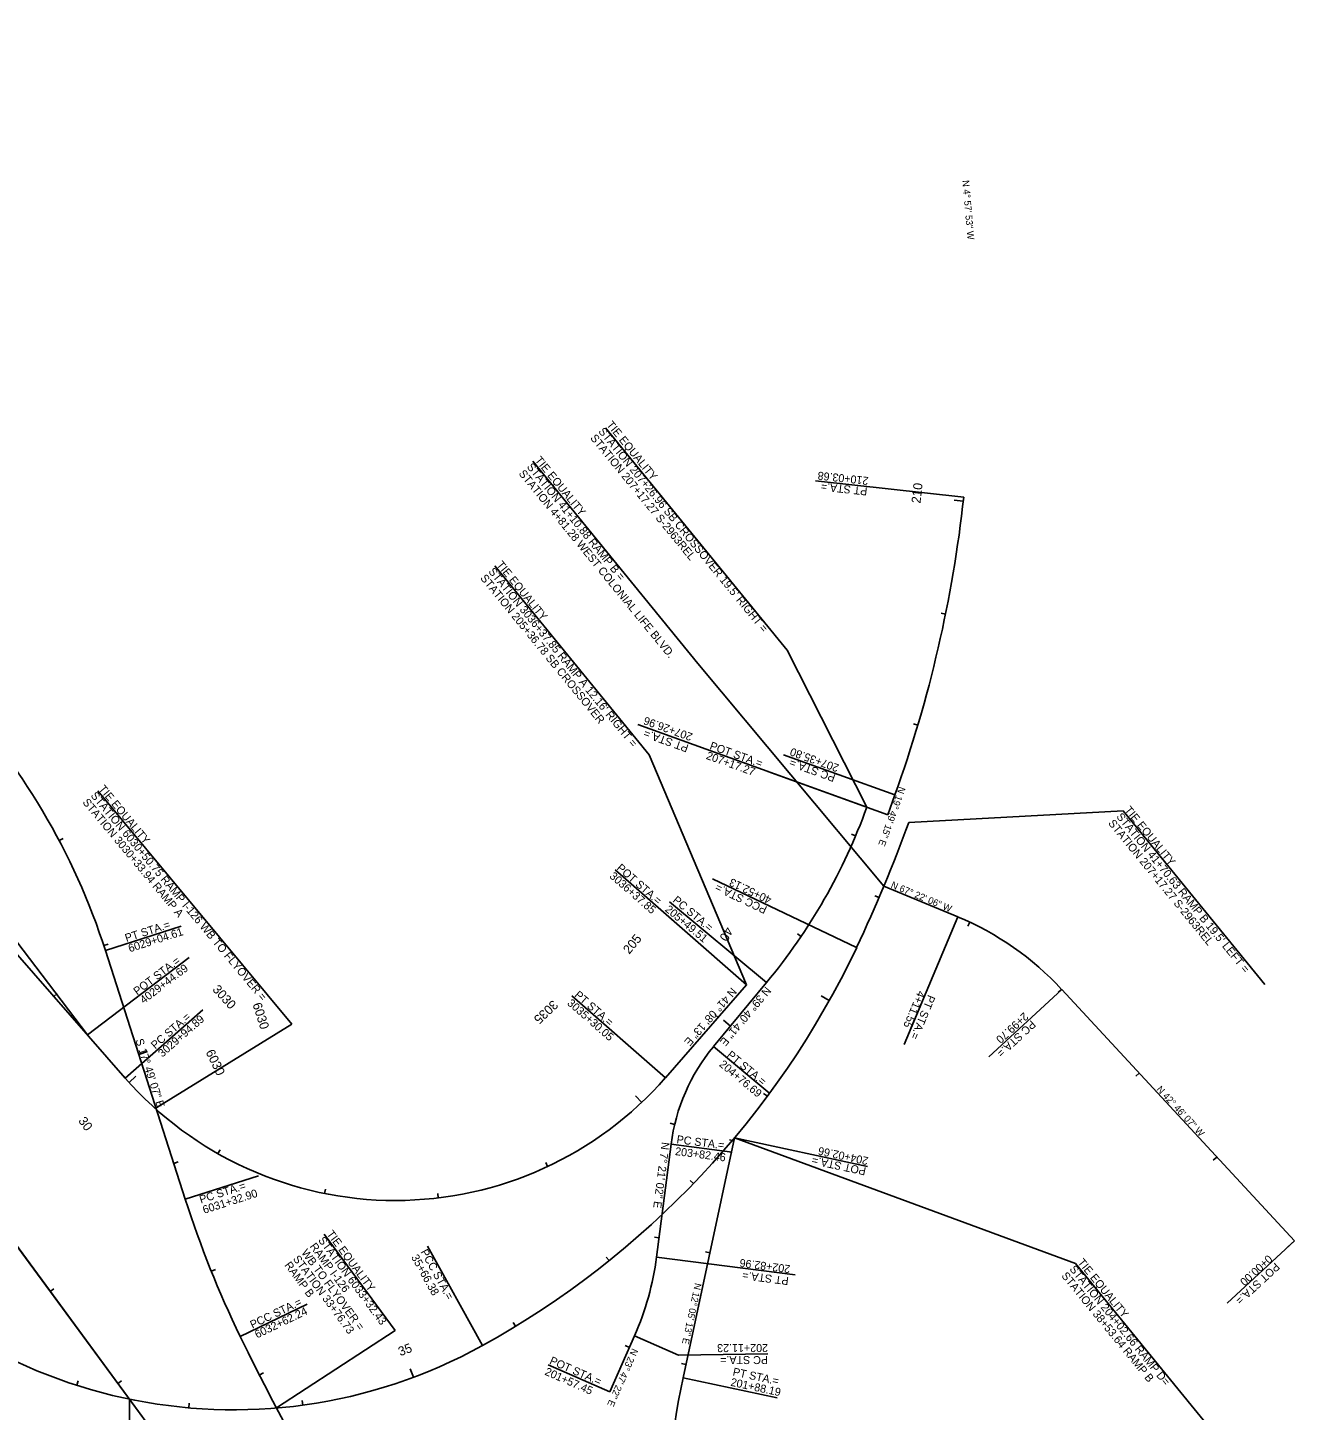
# Model space of a CAD drawing. Extents: x 1944333 to 1978554, y 788952 to 827675.
# Drawn here: x 1971031 to 1972139, y 796066 to 797275 of the extents above; entities that cross this region are included whole.
import ezdxf

# ---------------------------------------------------------------- set-up
doc = ezdxf.new("R2010")
doc.units = 0
for name, color, linetype in [('RD_HC_CL_Rel', 7, 'Continuous'), ('RD_HC_Data_Rel', 7, 'Continuous'), ('RD_HC_Data_Tic_Rel', 7, 'Continuous'), ('RD_HC_TX_Rel_Sta50', 7, 'Continuous')]:
    doc.layers.add(name, color=color, linetype=linetype)

msp = doc.modelspace()

# ---------------------------------------------------------------- linework, layer by layer
at = {"layer": 'RD_HC_CL_Rel'}
for p, q in [((1970235.6, 797274.6), (1971221.4, 795937.4)), ((1970468.6, 797095.3), (1971116, 796356.1)), ((1970486.6, 796934.2), (1971221.4, 795937.4)), ((1970763.6, 796814.3), (1971082.9, 796393.9)), ((1971783, 796586.3), (1971789.3, 796603.7)), ((1970944.7, 796575.9), (1971082.9, 796393.9)), ((1971844.2, 796497.1), (1971779.7, 796524)), ((1971098.7, 796467.5), (1971168.6, 796250.2)), ((1971588.7, 796356.4), (1971659.6, 796437.6)), ((1971630.6, 796383.6), (1971677.1, 796439.6)), ((1972138.7, 796213.6), (1971935.2, 796433.6)), ((1971604, 796094), (1971648.9, 796303.7)), ((1971580.8, 796199.6), (1971593.5, 796298.3)), ((1971539.9, 796081.6), (1971561.6, 796130.8))]:
    msp.add_line(p, q, dxfattribs=at)
for centre, radius, start, end in [((1970728.3, 796986.2), 1127.8, 340.1791, 353.7879), ((1970527.5, 796283.9), 600, 17.8187, 43.4833), ((1971283, 796766.5), 512, 320.322, 340.1791), ((1970655.5, 796992.7), 1218, 334.605, 340.1791), ((1971743.9, 796256.7), 260.5, 42.7685, 67.3684), ((1971051.2, 796804.8), 780, 298.9233, 334.605), ((1971759.1, 796276.9), 167, 140.322, 172.6496), ((1971352.2, 796563), 314, 221.212, 318.863), ((1971210.8, 796516), 450, 216.3977, 298.9233), ((1972056.8, 796535.7), 933, 197.8187, 205.7611), ((1971332.8, 796231.6), 250, 336.2104, 352.6496), ((1972855.7, 796921.2), 1820, 205.7611, 221.6884), ((1972226.6, 795960.7), 636.7, 167.9132, 225.4115)]:
    msp.add_arc(centre, radius, start, end, dxfattribs=at)
at = {"layer": 'RD_HC_Data_Rel'}
for p, q in [((1971536.1, 796924.8), (1971695, 796730.2)), ((1971472.6, 796895.5), (1971616.9, 796718.7)), ((1971849.5, 796864.1), (1971719.7, 796878.2)), ((1971439.4, 796803.9), (1971574.2, 796638.7)), ((1971764.7, 796592.9), (1971695, 796730.2)), ((1971779.7, 796524), (1971616.9, 796718.7)), ((1971764.7, 796592.9), (1971564.3, 796665.2)), ((1971659.6, 796437.6), (1971574.2, 796638.7)), ((1971789.3, 796603.7), (1971691.9, 796638.8)), ((1971783, 796586.3), (1971678, 796624.1)), ((1971261.7, 796403.1), (1971092.1, 796607.2)), ((1971988.8, 796589.8), (1971801.4, 796579.7)), ((1971988.8, 796589.8), (1972112.8, 796437.9)), ((1971659.6, 796437.6), (1971544.6, 796538.1)), ((1971755.8, 796470.3), (1971629.6, 796530.3)), ((1971677.1, 796439.6), (1971592.1, 796510.1)), ((1971844.2, 796497.1), (1971797.5, 796385.3)), ((1971098.7, 796467.5), (1971165, 796488.8)), ((1971082.9, 796393.9), (1971171.9, 796461.4)), ((1971588.7, 796356.4), (1971506.8, 796427.9)), ((1971935.2, 796433.6), (1971871.3, 796374.5)), ((1971116, 796356.1), (1971183.9, 796415.6)), ((1971142.3, 796329.4), (1971261.7, 796403.1)), ((1971630.6, 796383.6), (1971679.8, 796342.7)), ((1971648.9, 796303.7), (1971947.2, 796193.8)), ((1971648.9, 796303.7), (1971765.3, 796278.8)), ((1971593.5, 796298.3), (1971646.8, 796291.4)), ((1971168.6, 796250.2), (1971232.6, 796270.7)), ((1971352.2, 796135.3), (1971290.1, 796219.5)), ((1971428.5, 796122.1), (1971380.4, 796209.1)), ((1972138.7, 796213.6), (1972079.8, 796159.1)), ((1971580.8, 796199.6), (1971702, 796184)), ((1971947.2, 796193.8), (1972065.2, 796049.3)), ((1971216.6, 796130.2), (1971275.2, 796158.5)), ((1971248.3, 796067.6), (1971352.2, 796135.3)), ((1971561.6, 796130.8), (1971599.9, 796113.9)), ((1971599.9, 796113.9), (1971678, 796114.8)), ((1971539.9, 796081.6), (1971486.1, 796105.3)), ((1971604, 796094), (1971686.3, 796076.4)), ((1971119.7, 796075.3), (1971119.5, 796020.5))]:
    msp.add_line(p, q, dxfattribs=at)
at = {"layer": 'RD_HC_Data_Tic_Rel'}
for p, q in [((1971849.1, 796860.5), (1971841.2, 796861.3)), ((1971833.6, 796761.7), (1971829.7, 796762.5)), ((1971809.4, 796664.7), (1971805.5, 796665.9)), ((1971754.9, 796567.8), (1971751.2, 796569.4)), ((1971058.2, 796563.8), (1971061.8, 796565.7)), ((1971775.5, 796514), (1971771.8, 796515.5)), ((1971854.7, 796492.5), (1971853, 796488.8)), ((1971097.3, 796471.9), (1971101.1, 796473.2)), ((1971707.3, 796480), (1971704, 796482.2)), ((1971053.5, 796427.5), (1971056.5, 796430.1)), ((1971731.9, 796424), (1971724.9, 796427.9)), ((1971935, 796433.8), (1971932, 796431.1)), ((1971634.7, 796409.1), (1971631.7, 796411.7)), ((1971645.5, 796401.5), (1971639.3, 796406.6)), ((1971127.9, 796376.7), (1971135.5, 796379.2)), ((1971119.4, 796352.3), (1971125.3, 796357.6)), ((1972002.9, 796360.4), (1971999.9, 796357.7)), ((1971567.9, 796334.7), (1971562.4, 796340.6)), ((1971677.7, 796340.1), (1971674.4, 796342.5)), ((1971596.6, 796315.6), (1971592.7, 796316.5)), ((1971197, 796290), (1971199, 796293.4)), ((1971648.4, 796301.1), (1971644.5, 796302)), ((1971158.5, 796281.5), (1971162.3, 796282.7)), ((1971485.5, 796278.7), (1971483.8, 796282.3)), ((1972070.8, 796287), (1972067.8, 796284.3)), ((1971290.3, 796255.1), (1971291.1, 796259)), ((1971389.8, 796251.2), (1971389.4, 796255.2)), ((1971613.1, 796263.8), (1971610.2, 796266.6)), ((1971582.9, 796216.5), (1971579, 796217)), ((1972138.7, 796213.6), (1972132.8, 796208.1)), ((1971539.3, 796196.4), (1971536.8, 796199.6)), ((1971627.4, 796203.3), (1971623.5, 796204.2)), ((1971191.4, 796187.1), (1971195.1, 796188.6)), ((1971050.3, 796169.5), (1971053.5, 796171.9)), ((1971457.5, 796139), (1971455.4, 796142.4)), ((1971557, 796120.5), (1971553.4, 796122.1)), ((1971557, 796120.5), (1971553.4, 796122.1)), ((1971233.3, 796096.3), (1971236.9, 796098.2)), ((1971368.2, 796094.4), (1971365.4, 796101.9)), ((1971606.5, 796105.6), (1971602.6, 796106.4)), ((1971073.8, 796087.4), (1971075, 796091.2)), ((1971109.6, 796089), (1971112.9, 796091.4)), ((1971271.4, 796070.1), (1971270.9, 796074.1)), ((1971171.6, 796067.7), (1971172, 796071.7))]:
    msp.add_line(p, q, dxfattribs=at)

# ---------------------------------------------------------------- texts
at = {"layer": 'RD_HC_Data_Rel'}
for s, height, rotation, p in [('N 4%%d 57\' 53" W', 6, 274.9647, (1971848.2, 797141)), ("STATION 207+26.96 SB CROSSOVER 19.5' RIGHT =", 7, 309.2484, (1971529.5, 796921.4)), ('TIE EQUALITY', 7, 309.2484, (1971536.6, 796927.2)), ('STATION 207+17.27 S-2963REL', 7, 309.2484, (1971522.4, 796915.6)), ('TIE EQUALITY', 7, 309.2484, (1971474, 796896.2)), ('STATION 4+81.28 WEST COLONIAL LIFE BLVD.', 7, 309.2484, (1971459.8, 796884.5)), ('STATION 41+10.88 RAMP B =', 7, 309.2484, (1971466.9, 796890.4)), ('210+03.68', 7, 173.7879, (1971766.4, 796881.6)), ('PT STA.=', 7, 173.7879, (1971765.5, 796872.4)), ("STATION 3036+37.85 RAMP A 12.16' RIGHT =", 7, 309.2484, (1971433.3, 796798.9)), ('TIE EQUALITY', 7, 309.2484, (1971440.4, 796804.7)), ('STATION 205+36.78 SB CROSSOVER', 7, 309.2484, (1971426.2, 796793.1)), ('207+26.96', 7, 160.1791, (1971612.9, 796657.2)), ('PT STA.=', 7, 160.1791, (1971609.4, 796647.3)), ('POT STA.=', 7, 340.1792, (1971626.7, 796643.9)), ('207+35.80', 7, 160.1791, (1971741, 796630)), ('207+17.27', 7, 340.1792, (1971623.6, 796635.3)), ('PC STA.=', 7, 160.1791, (1971737.9, 796621.4)), ('STATION 6030+50.75 RAMP I-126 WB TO FLYOVER =', 7, 309.7574, (1971085.4, 796602.9)), ('TIE EQUALITY', 7, 309.7574, (1971092.4, 796608.7)), ('N 19%%d 49\' 15" E', 6, 250.1792, (1971793.1, 796611.4)), ('STATION 3030+33.94 RAMP A', 7, 309.7574, (1971078.3, 796597)), ('TIE EQUALITY', 7, 309.2484, (1971989.7, 796590.3)), ('STATION 207+17.27 S-2963REL', 7, 309.2484, (1971975.5, 796578.7)), ("STATION 41+70.63 RAMP B 19.5' LEFT =", 7, 309.2484, (1971982.6, 796584.5)), ('3036+37.85', 7, 318.863, (1971539.1, 796531.8)), ('POT STA.=', 7, 318.863, (1971545.3, 796538.9)), ('PCC STA.=', 7, 154.605, (1971678.1, 796505.7)), ('40+52.13', 7, 154.605, (1971682.1, 796514.2)), ('N 67%%d 22\' 06" W', 6, 337.3684, (1971785.2, 796522.8)), ('PC STA.=', 7, 320.322, (1971594.3, 796510.6)), ('205+49.51', 7, 320.322, (1971587.6, 796502.6)), ('PT STA.=', 7, 17.8187, (1971117.1, 796475)), ('6029+04.61', 7, 17.8187, (1971120, 796466)), ('POT STA.=', 7, 37.212, (1971126.5, 796428.2)), ('4029+44.69', 7, 37.212, (1971132.2, 796420.7)), ('3035+30.05', 7, 318.863, (1971502.1, 796420.7)), ('PT STA.=', 7, 318.863, (1971508.4, 796427.8)), ('N 41%%d 08\' 13" E', 7, 228.863, (1971646.3, 796435.8)), ('N 39%%d 40\' 41" E', 7, 230.322, (1971676.2, 796436.6)), ('4+11.55', 7, 247.3684, (1971809.6, 796433.1)), ('PT STA.=', 7, 247.3684, (1971818.4, 796429.4)), ('2+99.70', 7, 222.7685, (1971902.1, 796414)), ('PC STA.=', 7, 41.212, (1971142.3, 796381)), ('3029+94.89', 7, 41.212, (1971148.5, 796373.9)), ('PC STA.=', 7, 222.7685, (1971908.5, 796407.1)), ('S 17%%d 49\' 07" E', 7, 287.8187, (1971124.9, 796389.3)), ('PT STA.=', 7, 320.322, (1971641.7, 796375.2)), ('204+76.69', 7, 320.322, (1971635, 796367.1)), ('N 42%%d 46\' 07" W', 6, 312.7685, (1972017.7, 796345.9)), ('PC STA.=', 7, 352.6496, (1971598, 796299.2)), ('N 7%%d 21\' 02" E', 7, 262.6496, (1971585.3, 796300.4)), ('203+82.46', 7, 352.6496, (1971596.7, 796288.8)), ('204+02.66', 7, 167.9132, (1971766.5, 796286.7)), ('POT STA.=', 7, 167.9132, (1971764.5, 796277.7)), ('PC STA.=', 7, 17.8187, (1971182.2, 796246.3)), ('6031+32.90', 7, 17.8187, (1971185.1, 796237.3)), ('TIE EQUALITY', 7, 306.4178, (1971291.9, 796219.7)), ('WB TO FLYOVER =', 7, 306.4178, (1971269.7, 796203.3)), ('RAMP I-126', 7, 306.4178, (1971277.1, 796208.8)), ('STATION 6033+32.43', 7, 306.4178, (1971284.5, 796214.2)), ('PCC STA.=', 7, 298.9233, (1971374.1, 796204.1)), ('RAMP B', 7, 306.4178, (1971255, 796192.4)), ('STATION 33+76.73', 7, 306.4178, (1971262.4, 796197.9)), ('35+66.38', 7, 298.9233, (1971365.9, 796199.5)), ('202+82.96', 7, 172.6496, (1971698.1, 796192.3)), ('TIE EQUALITY', 7, 309.2484, (1971948.7, 796194.7)), ('POT STA.=', 7, 222.7685, (1972121.9, 796195.1)), ('0+00.00', 7, 222.7685, (1972115.5, 796202)), ('PT STA.=', 7, 172.6496, (1971696.7, 796181.9)), ('STATION 38+53.64 RAMP B', 7, 309.2484, (1971934.5, 796183)), ('STATION 204+02.66 RAMP D=', 7, 309.2484, (1971941.6, 796188.8)), ('N 12%%d 05\' 13" E', 6, 257.9132, (1971614.4, 796177.2)), ('PCC STA.=', 7, 25.7611, (1971227.3, 796136.8)), ('6032+62.24', 7, 25.7611, (1971231.4, 796128.3)), ('202+11.23', 7, 180.0869, (1971678.3, 796123.5)), ('POT STA.=', 7, 336.2104, (1971486.6, 796106.5)), ('N 23%%d 47\' 22" E', 6, 246.2104, (1971559.4, 796120.2)), ('PC STA.=', 7, 180.0869, (1971678.3, 796113)), ('201+57.45', 7, 336.2104, (1971482.4, 796096.9)), ('PT STA.=', 7, 347.9132, (1971647, 796096.1)), ('201+88.19', 7, 347.9132, (1971645.1, 796087.1))]:
    msp.add_text(s, height=height, rotation=rotation, dxfattribs=at).set_placement(p)
at = {"layer": 'RD_HC_TX_Rel_Sta50'}
for s, rotation, p in [('210', 83.6009, (1971811.6, 796858.3)), ('40', 240.7754, (1971641.3, 796489)), ('205', 50.322, (1971556.9, 796463.9)), ('3030', 312.1438, (1971191.8, 796433.2)), ('6030', 287.8187, (1971227.3, 796420.6)), ('3035', 223.3791, (1971490, 796424.8)), ('6030', 295.75, (1971186.2, 796378.8)), ('30', 306.3977, (1971074.6, 796318.6)), ('35', 20.4717, (1971356.6, 796112.8))]:
    msp.add_text(s, height=8, rotation=rotation, dxfattribs=at).set_placement(p)

doc.saveas('drawing.dxf')
